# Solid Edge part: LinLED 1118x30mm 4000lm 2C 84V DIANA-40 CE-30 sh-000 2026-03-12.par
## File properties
Author: robert.pupel
Template: iso metric part.par
Last saved by: robert.pupel
Revision: 1
Application: Solid Edge
Gęstość: 0.000 kg/m^3
Dokładność: 0.990
Username: robert.pupel
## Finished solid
Body 1: solid body, 14 faces, 28 edges, 16 vertices.
  Faces by surface: plane 14
  Edges by curve: line 28
Body 2: solid body, 14 faces, 28 edges, 16 vertices.
  Faces by surface: plane 14
  Edges by curve: line 28
Body 3: solid body, 67 faces, 258 edges, 194 vertices.
  Faces by surface: plane 55, cylinder 12
  Edges by curve: line 148, curve on surface 90, circle 12, ellipse 8
Body 4: solid body, 67 faces, 258 edges, 194 vertices.
  Faces by surface: plane 55, cylinder 12
  Edges by curve: line 148, curve on surface 90, circle 12, ellipse 8
Body 5: solid body, 67 faces, 258 edges, 194 vertices.
  Faces by surface: plane 55, cylinder 12
  Edges by curve: line 148, curve on surface 90, circle 12, ellipse 8
Body 6: solid body, 67 faces, 258 edges, 194 vertices.
  Faces by surface: plane 55, cylinder 12
  Edges by curve: line 148, curve on surface 90, circle 12, ellipse 8
Body 7: solid body, 67 faces, 258 edges, 194 vertices.
  Faces by surface: plane 55, cylinder 12
  Edges by curve: line 148, curve on surface 90, circle 12, ellipse 8
Body 8: solid body, 67 faces, 258 edges, 194 vertices.
  Faces by surface: plane 55, cylinder 12
  Edges by curve: line 148, curve on surface 90, circle 12, ellipse 8
Body 9: solid body, 67 faces, 258 edges, 194 vertices.
  Faces by surface: plane 55, cylinder 12
  Edges by curve: line 148, curve on surface 90, circle 12, ellipse 8
Body 10: solid body, 67 faces, 258 edges, 194 vertices.
  Faces by surface: plane 55, cylinder 12
  Edges by curve: line 148, curve on surface 90, circle 12, ellipse 8
Body 11: solid body, 67 faces, 258 edges, 194 vertices.
  Faces by surface: plane 55, cylinder 12
  Edges by curve: line 148, curve on surface 90, circle 12, ellipse 8
Body 12: solid body, 67 faces, 258 edges, 194 vertices.
  Faces by surface: plane 55, cylinder 12
  Edges by curve: line 148, curve on surface 90, circle 12, ellipse 8
Body 13: solid body, 67 faces, 258 edges, 194 vertices.
  Faces by surface: plane 55, cylinder 12
  Edges by curve: line 148, curve on surface 90, circle 12, ellipse 8
Body 14: solid body, 67 faces, 258 edges, 194 vertices.
  Faces by surface: plane 55, cylinder 12
  Edges by curve: line 148, curve on surface 90, circle 12, ellipse 8
Body 15: solid body, 67 faces, 258 edges, 194 vertices.
  Faces by surface: plane 55, cylinder 12
  Edges by curve: line 148, curve on surface 90, circle 12, ellipse 8
Body 16: solid body, 67 faces, 258 edges, 194 vertices.
  Faces by surface: plane 55, cylinder 12
  Edges by curve: line 148, curve on surface 90, circle 12, ellipse 8
Body 17: solid body, 67 faces, 258 edges, 194 vertices.
  Faces by surface: plane 55, cylinder 12
  Edges by curve: line 148, curve on surface 90, circle 12, ellipse 8
Body 18: solid body, 67 faces, 258 edges, 194 vertices.
  Faces by surface: plane 55, cylinder 12
  Edges by curve: line 148, curve on surface 90, circle 12, ellipse 8
Body 19: solid body, 67 faces, 258 edges, 194 vertices.
  Faces by surface: plane 55, cylinder 12
  Edges by curve: line 148, curve on surface 90, circle 12, ellipse 8
Body 20: solid body, 67 faces, 258 edges, 194 vertices.
  Faces by surface: plane 55, cylinder 12
  Edges by curve: line 148, curve on surface 90, circle 12, ellipse 8
Body 21: solid body, 67 faces, 258 edges, 194 vertices.
  Faces by surface: plane 55, cylinder 12
  Edges by curve: line 148, curve on surface 90, circle 12, ellipse 8
Body 22: solid body, 67 faces, 258 edges, 194 vertices.
  Faces by surface: plane 55, cylinder 12
  Edges by curve: line 148, curve on surface 90, circle 12, ellipse 8
Body 23: solid body, 67 faces, 258 edges, 194 vertices.
  Faces by surface: plane 55, cylinder 12
  Edges by curve: line 148, curve on surface 90, circle 12, ellipse 8
Body 24: solid body, 67 faces, 258 edges, 194 vertices.
  Faces by surface: plane 55, cylinder 12
  Edges by curve: line 148, curve on surface 90, circle 12, ellipse 8
Body 25: solid body, 67 faces, 258 edges, 194 vertices.
  Faces by surface: plane 55, cylinder 12
  Edges by curve: line 148, curve on surface 90, circle 12, ellipse 8
Body 26: solid body, 67 faces, 258 edges, 194 vertices.
  Faces by surface: plane 55, cylinder 12
  Edges by curve: line 148, curve on surface 90, circle 12, ellipse 8
Body 27: solid body, 67 faces, 258 edges, 194 vertices.
  Faces by surface: plane 55, cylinder 12
  Edges by curve: line 148, curve on surface 90, circle 12, ellipse 8
Body 28: solid body, 67 faces, 258 edges, 194 vertices.
  Faces by surface: plane 55, cylinder 12
  Edges by curve: line 148, curve on surface 90, circle 12, ellipse 8
Body 29: solid body, 67 faces, 258 edges, 194 vertices.
  Faces by surface: plane 55, cylinder 12
  Edges by curve: line 148, curve on surface 90, circle 12, ellipse 8
Body 30: solid body, 67 faces, 258 edges, 194 vertices.
  Faces by surface: plane 55, cylinder 12
  Edges by curve: line 148, curve on surface 90, circle 12, ellipse 8
Body 31: solid body, 67 faces, 258 edges, 194 vertices.
  Faces by surface: plane 55, cylinder 12
  Edges by curve: line 148, curve on surface 90, circle 12, ellipse 8
Body 32: solid body, 67 faces, 258 edges, 194 vertices.
  Faces by surface: plane 55, cylinder 12
  Edges by curve: line 148, curve on surface 90, circle 12, ellipse 8
Body 33: solid body, 67 faces, 258 edges, 194 vertices.
  Faces by surface: plane 55, cylinder 12
  Edges by curve: line 148, curve on surface 90, circle 12, ellipse 8
Body 34: solid body, 67 faces, 258 edges, 194 vertices.
  Faces by surface: plane 55, cylinder 12
  Edges by curve: line 148, curve on surface 90, circle 12, ellipse 8
Body 35: solid body, 67 faces, 258 edges, 194 vertices.
  Faces by surface: plane 55, cylinder 12
  Edges by curve: line 148, curve on surface 90, circle 12, ellipse 8
Body 36: solid body, 67 faces, 258 edges, 194 vertices.
  Faces by surface: plane 55, cylinder 12
  Edges by curve: line 148, curve on surface 90, circle 12, ellipse 8
Body 37: solid body, 67 faces, 258 edges, 194 vertices.
  Faces by surface: plane 55, cylinder 12
  Edges by curve: line 148, curve on surface 90, circle 12, ellipse 8
Body 38: solid body, 67 faces, 258 edges, 194 vertices.
  Faces by surface: plane 55, cylinder 12
  Edges by curve: line 148, curve on surface 90, circle 12, ellipse 8
Body 39: solid body, 67 faces, 258 edges, 194 vertices.
  Faces by surface: plane 55, cylinder 12
  Edges by curve: line 148, curve on surface 90, circle 12, ellipse 8
Body 40: solid body, 67 faces, 258 edges, 194 vertices.
  Faces by surface: plane 55, cylinder 12
  Edges by curve: line 148, curve on surface 90, circle 12, ellipse 8
Body 41: solid body, 67 faces, 258 edges, 194 vertices.
  Faces by surface: plane 55, cylinder 12
  Edges by curve: line 148, curve on surface 90, circle 12, ellipse 8
Body 42: solid body, 67 faces, 258 edges, 194 vertices.
  Faces by surface: plane 55, cylinder 12
  Edges by curve: line 148, curve on surface 90, circle 12, ellipse 8
Body 43: solid body, 67 faces, 258 edges, 194 vertices.
  Faces by surface: plane 55, cylinder 12
  Edges by curve: line 148, curve on surface 90, circle 12, ellipse 8
Body 44: solid body, 67 faces, 258 edges, 194 vertices.
  Faces by surface: plane 55, cylinder 12
  Edges by curve: line 148, curve on surface 90, circle 12, ellipse 8
Body 45: solid body, 67 faces, 258 edges, 194 vertices.
  Faces by surface: plane 55, cylinder 12
  Edges by curve: line 148, curve on surface 90, circle 12, ellipse 8
Body 46: solid body, 67 faces, 258 edges, 194 vertices.
  Faces by surface: plane 55, cylinder 12
  Edges by curve: line 148, curve on surface 90, circle 12, ellipse 8
Body 47: solid body, 67 faces, 258 edges, 194 vertices.
  Faces by surface: plane 55, cylinder 12
  Edges by curve: line 148, curve on surface 90, circle 12, ellipse 8
Body 48: solid body, 67 faces, 258 edges, 194 vertices.
  Faces by surface: plane 55, cylinder 12
  Edges by curve: line 148, curve on surface 90, circle 12, ellipse 8
Body 49: solid body, 67 faces, 258 edges, 194 vertices.
  Faces by surface: plane 55, cylinder 12
  Edges by curve: line 148, curve on surface 90, circle 12, ellipse 8
Body 50: solid body, 67 faces, 258 edges, 194 vertices.
  Faces by surface: plane 55, cylinder 12
  Edges by curve: line 148, curve on surface 90, circle 12, ellipse 8
Body 51: solid body, 67 faces, 258 edges, 194 vertices.
  Faces by surface: plane 55, cylinder 12
  Edges by curve: line 148, curve on surface 90, circle 12, ellipse 8
Body 52: solid body, 67 faces, 258 edges, 194 vertices.
  Faces by surface: plane 55, cylinder 12
  Edges by curve: line 148, curve on surface 90, circle 12, ellipse 8
Body 53: solid body, 67 faces, 258 edges, 194 vertices.
  Faces by surface: plane 55, cylinder 12
  Edges by curve: line 148, curve on surface 90, circle 12, ellipse 8
Body 54: solid body, 67 faces, 258 edges, 194 vertices.
  Faces by surface: plane 55, cylinder 12
  Edges by curve: line 148, curve on surface 90, circle 12, ellipse 8
Body 55: solid body, 67 faces, 258 edges, 194 vertices.
  Faces by surface: plane 55, cylinder 12
  Edges by curve: line 148, curve on surface 90, circle 12, ellipse 8
Body 56: solid body, 67 faces, 258 edges, 194 vertices.
  Faces by surface: plane 55, cylinder 12
  Edges by curve: line 148, curve on surface 90, circle 12, ellipse 8
Body 57: solid body, 67 faces, 258 edges, 194 vertices.
  Faces by surface: plane 55, cylinder 12
  Edges by curve: line 148, curve on surface 90, circle 12, ellipse 8
Body 58: solid body, 67 faces, 258 edges, 194 vertices.
  Faces by surface: plane 55, cylinder 12
  Edges by curve: line 148, curve on surface 90, circle 12, ellipse 8
Body 59: solid body, 67 faces, 258 edges, 194 vertices.
  Faces by surface: plane 55, cylinder 12
  Edges by curve: line 148, curve on surface 90, circle 12, ellipse 8
Body 60: solid body, 67 faces, 258 edges, 194 vertices.
  Faces by surface: plane 55, cylinder 12
  Edges by curve: line 148, curve on surface 90, circle 12, ellipse 8
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Bounding box of the edges (mm; curved faces can reach further): 1118.000 x 4.450 x 30.000, from (-559, -3.45, -15) to (559, 1, 15).
Cylindrical faces by radius (mm): R0.2 x942, R0.2169 x6, R0.25 x348, R0.3373 x6, R0.35 x112, R0.4 x8, R0.4006 x2, R0.4008 x2, R0.525 x2, R0.6 x20, R1 x8, R1.025 x32, R1.05 x4, R1.1 x4, R1.1989 x2, R1.199 x2, R1.2 x10, R1.5309 x2, R1.5312 x2, R1.65 x32, R1.7414 x2, R1.7423 x2
Conical faces (half-angle, radius in mm at the cone's reference point): 0.398 deg R1.1964 x2, 0.4493 deg R1.1964 x2, 0.4746 deg R1.1948 x2, 0.4758 deg R1.1948 x2, 0.5 deg R0.5056 x4, 0.5 deg R1.0082 x4, 1 deg R0.5511 x2, 10 deg R0.2132 x4, 10 deg R0.4132 x4, 16.0099 deg R1.1053 x2, 16.1249 deg R1.1279 x2, 18.8604 deg R1.0669 x4, 19.5041 deg R0.5138 x2, 19.8244 deg R0.5099 x2, 27.363 deg R0.6214 x2, 40.6434 deg R0.5161 x2, 43.3309 deg R0.4892 x2, 45 deg R0.575 x2, 45 deg R0.625 x4
Toroidal faces (ring radius, tube radius in mm): R0.0958 r0.3997 x4, R0.1076 r0.4 x2, R0.1101 r0.4001 x2, R0.1217 r0.4 x2, R0.1234 r0.4 x2, R0.1626 r0.228 x2, R0.1634 r0.2287 x2, R0.3287 r0.2001 x2, R0.3684 r0.2151 x2, R0.3703 r0.4 x2, R0.3818 r0.2 x4, R0.4166 r0.3983 x2, R0.5981 r0.197 x2, R0.5982 r0.197 x2, R0.6009 r0.3968 x2, R0.6009 r0.3969 x2, R0.6227 r0.2 x2, R0.6235 r0.2 x2, R0.8 r0.2 x4, R0.8522 r0.3 x2, R0.9002 r0.2 x2, R0.9018 r0.2 x2, R0.9197 r0.223 x2, R0.9365 r0.2 x2, R0.9663 r0.2263 x2, R0.9665 r0.2263 x2, R1.429 r1.2 x2, R1.8741 r0.2175 x2, R1.9007 r0.2 x2
Spherical faces by radius (mm): R0.2 x12, R0.6 x4
Planar faces by outward normal: +x 918, +y 579, +z 1183, -x 918, -y 1045, -z 1183, oblique 652
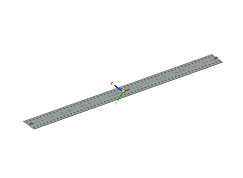
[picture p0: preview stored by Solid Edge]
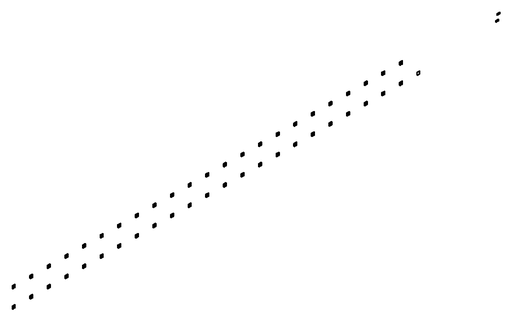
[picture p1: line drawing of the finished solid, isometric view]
